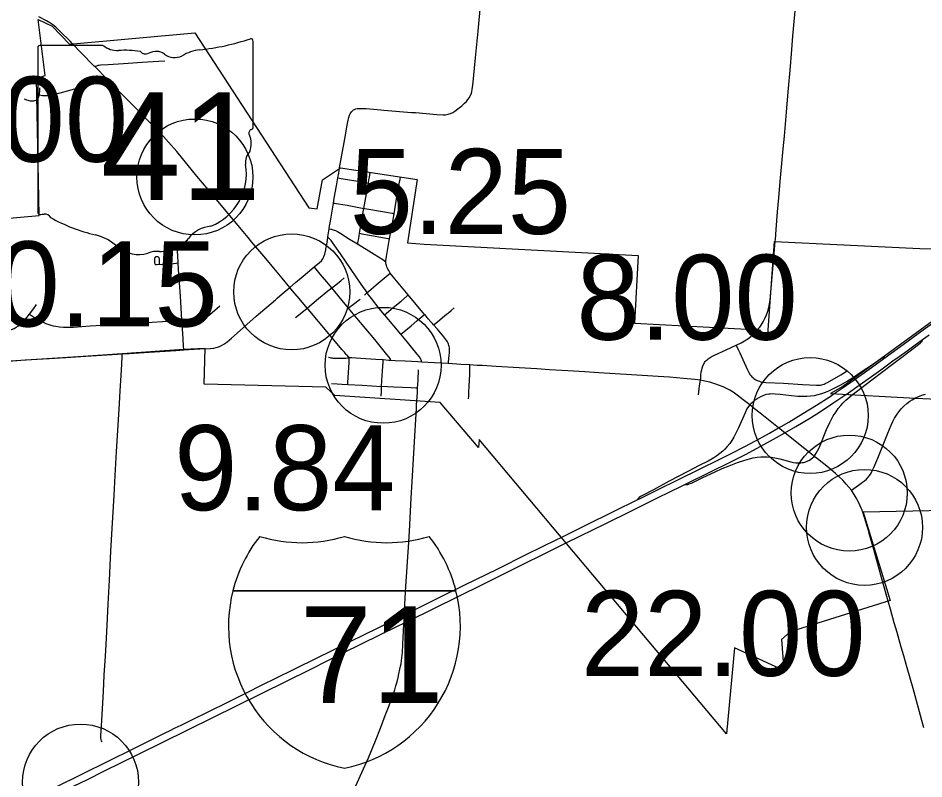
# Model space of a CAD drawing. Extents: x 1597222 to 1925846, y 496284 to 911751.
# Drawn here: x 1665653 to 1677369, y 597821 to 607664 of the extents above; entities that cross this region are included whole.
import ezdxf

# ---------------------------------------------------------------- set-up
doc = ezdxf.new("R2010")
doc.units = 0
for name, color, linetype in [('Default', 7, 'Continuous'), ('GM_X_City_Street', 7, 'Continuous'), ('GM_X_Corporation', 7, 'Continuous'), ('GM_X_County_Road', 7, 'Continuous'), ('GM_X_Interchange_Ramps', 7, 'Continuous'), ('GM_X_Interstate_Route', 7, 'Continuous'), ('GM_X_Interstate_Shield', 7, 'Continuous'), ('GM_X_State_Route', 7, 'Continuous'), ('GM_X_State_Shield', 7, 'Continuous'), ('GM_X_Township_Road', 7, 'Continuous')]:
    doc.layers.add(name, color=color, linetype=linetype)

msp = doc.modelspace()

# ---------------------------------------------------------------- linework, layer by layer
at = {"layer": 'Default'}
for centre in [(1667939, 605609), (1667939, 605609), (1669192, 604122), (1669192, 604122), (1669192, 604122), (1669192, 604122), (1670374, 603172), (1670374, 603172), (1675899, 602522), (1675899, 602522), (1676404, 601519), (1676404, 601519), (1676602, 601075), (1676602, 601075), (1666460, 597780), (1666460, 597780)]:
    msp.add_circle(centre, 750, dxfattribs=at)
at = {"layer": 'GM_X_City_Street'}
for points in [[(1666641, 607041), (1666672, 607049), (1666688, 607054), (1666701, 607056), (1666720, 607059), (1666818, 607066), (1667014, 607078), (1667258, 607094), (1667470, 607107), (1667552, 607113)], [(1665928, 606671), (1665968, 606664), (1665983, 606662), (1666000, 606661), (1666033, 606661), (1666065, 606665), (1666114, 606675), (1666195, 606696), (1666385, 606749), (1666626, 606814), (1666755, 606849), (1666811, 606868)], [(1665928, 606671), (1665929, 606681), (1665934, 606729), (1665935, 606761)], [(1665733, 606621), (1665762, 606608), (1665777, 606602), (1665793, 606598), (1665808, 606594), (1665823, 606593), (1665839, 606593), (1665855, 606595), (1665870, 606598), (1665884, 606604), (1665897, 606612), (1665907, 606624), (1665915, 606637), (1665922, 606651), (1665926, 606662), (1665928, 606671)], [(1670183, 605530), (1670190, 605571), (1670197, 605608), (1670207, 605668)], [(1669789, 605598), (1669830, 605591), (1670103, 605544), (1670183, 605530)], [(1670125, 605203), (1670150, 605345), (1670183, 605530)], [(1670183, 605530), (1670343, 605501), (1670472, 605479), (1670553, 605463), (1670573, 605459)], [(1670573, 605459), (1670578, 605490), (1670588, 605548), (1670593, 605577), (1670599, 605609)], [(1670516, 605134), (1670524, 605186), (1670544, 605298), (1670558, 605379), (1670573, 605459)], [(1669732, 605271), (1669745, 605269), (1669767, 605266), (1669799, 605261), (1669911, 605242), (1670125, 605203)], [(1670070, 604880), (1670075, 604909), (1670113, 605135), (1670125, 605203)], [(1670125, 605203), (1670136, 605201), (1670393, 605156), (1670490, 605139), (1670516, 605134)], [(1670458, 604810), (1670495, 605011), (1670516, 605134)], [(1669676, 604938), (1669696, 604934), (1669707, 604932), (1669717, 604929), (1669728, 604927), (1669742, 604922), (1669757, 604917), (1669786, 604902), (1669828, 604877), (1669939, 604806), (1670023, 604755), (1670042, 604743)], [(1670167, 604112), (1670090, 604223), (1669961, 604412), (1669823, 604614), (1669749, 604720), (1669720, 604761), (1669700, 604786), (1669674, 604818), (1669661, 604833)], [(1670042, 604743), (1670045, 604757), (1670050, 604779), (1670058, 604811), (1670070, 604880)], [(1670070, 604880), (1670099, 604874), (1670196, 604856), (1670390, 604821), (1670439, 604813), (1670458, 604810)], [(1670042, 604743), (1670190, 604652), (1670259, 604609), (1670370, 604541), (1670410, 604513)], [(1670410, 604513), (1670411, 604528), (1670413, 604550), (1670416, 604578), (1670431, 604658), (1670454, 604787), (1670458, 604810)], [(1667723, 604496), (1667718, 604592), (1667710, 604691)], [(1667481, 604482), (1667480, 604531), (1667480, 604547), (1667480, 604551), (1667479, 604557), (1667477, 604563), (1667472, 604569), (1667468, 604572), (1667464, 604574), (1667461, 604575), (1667456, 604576), (1667449, 604577), (1667444, 604577), (1667441, 604577), (1667437, 604577), (1667434, 604575), (1667430, 604573), (1667426, 604570), (1667422, 604565), (1667420, 604561), (1667418, 604555), (1667416, 604549), (1667416, 604545), (1667415, 604533), (1667415, 604522), (1667415, 604508), (1667416, 604500), (1667419, 604491), (1667422, 604485), (1667424, 604482), (1667428, 604479), (1667431, 604477), (1667434, 604476), (1667438, 604476), (1667443, 604475), (1667451, 604475), (1667663, 604491), (1667696, 604494), (1667723, 604496)], [(1667771, 603755), (1667761, 603917), (1667751, 604065), (1667728, 604411), (1667723, 604496)], [(1670465, 604364), (1670456, 604380), (1670446, 604397), (1670437, 604416), (1670430, 604431), (1670424, 604447), (1670419, 604463), (1670414, 604478), (1670411, 604497), (1670410, 604513)], [(1669709, 604174), (1669646, 604251), (1669560, 604352), (1669507, 604415), (1669482, 604445)], [(1670167, 604112), (1670184, 604126), (1670285, 604214), (1670465, 604364)], [(1670698, 604083), (1670527, 604291), (1670465, 604364)], [(1669709, 604174), (1669744, 604201), (1669826, 604266), (1669872, 604304)], [(1669392, 603913), (1669452, 603964), (1669539, 604035), (1669661, 604135), (1669709, 604174)], [(1669926, 603912), (1669843, 604010), (1669709, 604174)], [(1670133, 604081), (1670167, 604112)], [(1670391, 603827), (1670324, 603909), (1670223, 604037), (1670174, 604102), (1670167, 604112)], [(1669926, 603912), (1669941, 603924), (1669991, 603962), (1670066, 604021), (1670078, 604030)], [(1670391, 603827), (1670417, 603848), (1670505, 603920), (1670607, 604002), (1670680, 604067), (1670698, 604083)], [(1670910, 603831), (1670698, 604083)], [(1665799, 603835), (1665842, 603890), (1665890, 603957)], [(1667771, 603755), (1667806, 603757), (1667871, 603761), (1667970, 603767), (1668003, 603771), (1668019, 603774), (1668036, 603779), (1668052, 603784), (1668082, 603797), (1668111, 603813), (1668139, 603833), (1668164, 603854), (1668263, 603941)], [(1669241, 603790), (1669367, 603892), (1669392, 603913)], [(1670472, 603235), (1670464, 603260), (1670453, 603276), (1670421, 603313), (1670319, 603443), (1670267, 603506), (1670035, 603784), (1669926, 603912)], [(1671026, 603696), (1671055, 603719), (1671082, 603739), (1671170, 603811), (1671196, 603832), (1671219, 603851), (1671256, 603882), (1671294, 603916)], [(1665330, 603602), (1665359, 603603), (1665408, 603604), (1665458, 603609), (1665506, 603617), (1665538, 603625), (1665569, 603637), (1665600, 603650), (1665629, 603665), (1665657, 603683), (1665683, 603703), (1665708, 603724), (1665730, 603746), (1665744, 603763), (1665752, 603774), (1665799, 603835)], [(1665799, 603835), (1665824, 603818), (1665837, 603808), (1665878, 603780), (1665922, 603755), (1665966, 603734), (1666012, 603715), (1666075, 603693), (1666107, 603684), (1666140, 603678), (1666189, 603671), (1666238, 603666), (1666288, 603664), (1666370, 603667), (1666584, 603681), (1666896, 603700), (1667143, 603717), (1667324, 603728), (1667587, 603745), (1667734, 603753), (1667771, 603755)], [(1670603, 603575), (1670512, 603683), (1670397, 603821), (1670391, 603827)], [(1670603, 603575), (1670621, 603589), (1670736, 603684), (1670812, 603748), (1670888, 603812), (1670910, 603831)], [(1671026, 603696), (1671012, 603711), (1670990, 603735), (1670958, 603772), (1670917, 603824), (1670910, 603831)], [(1667795, 603371), (1667792, 603423), (1667782, 603588), (1667772, 603736), (1667771, 603755)], [(1671220, 603194), (1671222, 603216), (1671229, 603299), (1671231, 603334), (1671233, 603368), (1671231, 603398), (1671229, 603414), (1671225, 603429), (1671221, 603445), (1671215, 603459), (1671207, 603474), (1671199, 603487), (1671160, 603540), (1671076, 603639), (1671026, 603696)], [(1670870, 603214), (1670871, 603229), (1670867, 603242), (1670863, 603252), (1670843, 603282), (1670813, 603317), (1670741, 603407), (1670690, 603470), (1670603, 603575)], [(1674940, 603433), (1675004, 603463), (1675048, 603487), (1675090, 603513), (1675129, 603543), (1675158, 603569), (1675181, 603591), (1675209, 603621), (1675220, 603634)], [(1674479, 602981), (1674482, 603012), (1674485, 603057), (1674487, 603074), (1674489, 603088), (1674495, 603114), (1674501, 603136), (1674511, 603166), (1674525, 603195), (1674533, 603209), (1674542, 603222), (1674553, 603234), (1674564, 603245), (1674577, 603255), (1674590, 603265), (1674618, 603281), (1674661, 603304), (1674810, 603373), (1674940, 603433)], [(1674940, 603433), (1674967, 603377), (1674988, 603332), (1675084, 603122), (1675106, 603078), (1675124, 603050), (1675134, 603037), (1675145, 603025), (1675157, 603014), (1675169, 603003), (1675183, 602994), (1675197, 602985), (1675211, 602977), (1675226, 602970), (1675242, 602965), (1675258, 602960), (1675290, 602954), (1675323, 602950), (1675553, 602939), (1675800, 602924), (1675981, 602915), (1676014, 602915), (1676030, 602916), (1676046, 602919), (1676062, 602923), (1676078, 602928), (1676093, 602935), (1676122, 602950), (1676294, 603047), (1676378, 603100)], [(1669668, 603279), (1669683, 603274), (1669698, 603270), (1669715, 603267), (1669728, 603265), (1669740, 603264), (1669761, 603264), (1669809, 603263), (1669859, 603264), (1669891, 603265), (1669912, 603267), (1669937, 603270)], [(1669916, 602924), (1669918, 602950), (1669926, 603080), (1669934, 603210), (1669937, 603270)], [(1671480, 602739), (1671482, 602773), (1671485, 602823), (1671488, 602904), (1671495, 603054), (1671497, 603118), (1671498, 603156), (1671498, 603177)], [(1670820, 602877), (1670827, 602979), (1670833, 603114)], [(1674455, 602789), (1674465, 602908), (1674479, 602981)], [(1669708, 602936), (1669778, 602931), (1669842, 602928), (1669916, 602924)], [(1669916, 602924), (1670101, 602913), (1670355, 602899)], [(1670351, 602773), (1670353, 602839), (1670355, 602899)]]:
    msp.add_lwpolyline(points, dxfattribs=at)
at = {"layer": 'GM_X_Corporation'}
for points in [[(1664571, 604990), (1665925, 605111), (1665891, 606881), (1666004, 606922), (1665913, 607646), (1666092, 607560), (1666317, 607328), (1667939, 607472), (1669413, 605210), (1669522, 605195), (1669588, 605574), (1669821, 605726), (1670815, 605575), (1670690, 604758), (1670905, 604739), (1673675, 604592), (1673628, 603718), (1675241, 603632), (1675327, 603511), (1675347, 603509), (1675411, 604413), (1675419, 604540), (1675435, 604774), (1677319, 604682), (1677768, 604673)], [(1677671, 603881), (1676320, 602899), (1676161, 602808), (1677259, 602749), (1677731, 602724)], [(1677655, 601292), (1676583, 601273), (1676933, 600130), (1675641, 599722), (1675527, 599624), (1675558, 599225), (1674921, 599515), (1674815, 598405), (1672746, 600866), (1671617, 602210), (1671609, 602108), (1671110, 602693), (1669750, 602781), (1669632, 602889), (1668058, 602929), (1668072, 603390), (1667791, 603376), (1666999, 603320), (1666560, 603289), (1665960, 603252), (1665349, 603213)]]:
    msp.add_lwpolyline(points, dxfattribs=at)
at = {"layer": 'GM_X_County_Road'}
for points in [[(1675445, 604774), (1675448, 604798), (1675458, 604929), (1675477, 605158), (1675493, 605338), (1675512, 605550), (1675541, 605877), (1675551, 605975), (1675566, 606138), (1675593, 606449), (1675615, 606711), (1675643, 607038), (1675657, 607201), (1675676, 607430), (1675716, 607904), (1675738, 608150), (1675755, 608362), (1675801, 608885), (1675813, 609029)], [(1675220, 603634), (1675234, 603651), (1675246, 603666), (1675264, 603691), (1675290, 603734), (1675313, 603778), (1675333, 603824), (1675350, 603871), (1675363, 603919), (1675373, 603968), (1675380, 604017), (1675445, 604774)]]:
    msp.add_lwpolyline(points, dxfattribs=at)
at = {"layer": 'GM_X_Interchange_Ramps'}
for points in [[(1675951, 601994), (1675977, 602034), (1675995, 602067), (1676020, 602115), (1676111, 602340), (1676151, 602430), (1676173, 602474), (1676197, 602517), (1676233, 602572), (1676262, 602612), (1676293, 602650), (1676326, 602687), (1676360, 602722), (1676410, 602765), (1676444, 602793), (1676474, 602817), (1676697, 602986), (1676944, 603172), (1677100, 603289), (1677323, 603458), (1677339, 603474), (1677345, 603480), (1677349, 603487), (1677352, 603496), (1677353, 603507)], [(1676869, 603273), (1676854, 603271), (1676839, 603267), (1676825, 603261), (1676809, 603252), (1676729, 603197), (1676534, 603064), (1676466, 603019), (1676382, 602968), (1676282, 602911), (1676195, 602866), (1676136, 602838), (1676091, 602819), (1676045, 602802), (1675998, 602789), (1675950, 602778), (1675901, 602771), (1675853, 602768), (1675803, 602767), (1675738, 602770), (1675657, 602778), (1675511, 602795), (1675445, 602800), (1675413, 602801), (1675380, 602800), (1675364, 602799), (1675332, 602793), (1675316, 602789), (1675285, 602778), (1675256, 602763), (1675227, 602747), (1675173, 602711), (1675155, 602695), (1675135, 602678), (1675116, 602660)], [(1675116, 602660), (1675100, 602637), (1675081, 602607), (1675058, 602557), (1674972, 602361), (1674943, 602301), (1674912, 602243), (1674886, 602201), (1674857, 602161), (1674826, 602123), (1674793, 602086), (1674769, 602063), (1674731, 602032), (1674691, 602002), (1674650, 601975), (1674579, 601933), (1674461, 601874), (1674317, 601800), (1674074, 601671), (1673871, 601563), (1673731, 601489), (1673704, 601474), (1673687, 601463), (1673673, 601449), (1673662, 601432)], [(1674279, 601631), (1674301, 601629), (1674308, 601630), (1674317, 601631), (1674335, 601637), (1674363, 601649), (1674509, 601720), (1674668, 601795), (1674759, 601835), (1674850, 601873), (1674958, 601913), (1675052, 601944), (1675115, 601963), (1675163, 601974), (1675212, 601982), (1675261, 601987), (1675294, 601989), (1675343, 601988), (1675392, 601983), (1675441, 601975), (1675505, 601961), (1675649, 601923), (1675681, 601916), (1675714, 601912), (1675746, 601910), (1675779, 601911), (1675796, 601913), (1675812, 601916), (1675828, 601920), (1675859, 601931), (1675888, 601946), (1675927, 601976), (1675951, 601994)]]:
    msp.add_lwpolyline(points, dxfattribs=at)
at = {"layer": 'GM_X_Interstate_Route'}
for points in [[(1666117, 597705), (1666485, 597888), (1667151, 598216), (1667286, 598282), (1667563, 598419), (1667611, 598444), (1667686, 598481), (1667761, 598518), (1667918, 598595), (1668093, 598680), (1668391, 598828), (1668640, 598951), (1668777, 599019), (1669021, 599141), (1669199, 599227), (1669554, 599403), (1669671, 599460), (1669991, 599619), (1670083, 599664), (1670152, 599698), (1670285, 599764), (1670649, 599944), (1671081, 600157), (1671424, 600327), (1671856, 600540), (1672233, 600727), (1672620, 600918), (1672679, 600946), (1672989, 601100), (1673362, 601284), (1673662, 601432), (1673708, 601454), (1673923, 601559), (1674204, 601700), (1674456, 601824), (1674737, 601962), (1674867, 602026), (1675052, 602120), (1675192, 602195), (1675288, 602248), (1675372, 602294), (1675490, 602361), (1675525, 602381), (1675623, 602437), (1675805, 602548), (1675982, 602656), (1676155, 602769), (1676208, 602806), (1676324, 602886), (1676469, 602984), (1676662, 603121), (1676835, 603248), (1676869, 603273), (1677103, 603441), (1677359, 603629), (1677679, 603859)], [(1676363, 602796), (1676534, 602915), (1676692, 603028), (1676811, 603114), (1676968, 603228), (1677048, 603286), (1677151, 603361), (1677258, 603438), (1677353, 603507), (1677438, 603568)], [(1672742, 600873), (1672926, 600964), (1673246, 601123), (1673588, 601291), (1673966, 601477), (1674041, 601514), (1674279, 601631), (1674312, 601647), (1674870, 601924), (1675061, 602020), (1675261, 602125), (1675462, 602236), (1675570, 602298), (1675712, 602380), (1675901, 602494), (1676031, 602576), (1676204, 602689), (1676348, 602786), (1676363, 602796)], [(1670626, 599828), (1670644, 599837), (1670708, 599868), (1671352, 600186), (1671658, 600338), (1672126, 600569), (1672508, 600758), (1672742, 600873)], [(1664380, 596744), (1665760, 597422), (1666351, 597716), (1666379, 597730), (1666540, 597810), (1666769, 597923), (1667210, 598141), (1669437, 599241), (1669660, 599351), (1669859, 599450), (1670569, 599801), (1670626, 599828)]]:
    msp.add_lwpolyline(points, dxfattribs=at)
at = {"layer": 'GM_X_Interstate_Shield'}
for p, q in [((1668432, 600256), (1671317, 600256)), ((1671317, 600256), (1668432, 600256)), ((1671317, 600256), (1668432, 600256))]:
    msp.add_line(p, q, dxfattribs=at)
for centre, start, end in [((1670249, 599796), 141.669, 165.8066), ((1669327, 602752), 253.0091, 286.9909), ((1670422, 602752), 253.0091, 286.9909), ((1669499, 599796), 14.1934, 38.331), ((1670249, 599796), 165.8066, 258.463), ((1669499, 599796), 281.537, 14.1934)]:
    msp.add_arc(centre, 1875, start, end, dxfattribs=at)
at = {"layer": 'GM_X_State_Route'}
for points in [[(1669812, 605729), (1669879, 606103), (1669911, 606280), (1669923, 606345), (1669930, 606377), (1669940, 606409), (1669947, 606425), (1669955, 606439), (1669965, 606453), (1669977, 606466), (1669990, 606476), (1670005, 606484), (1670021, 606490), (1670038, 606494), (1670054, 606496), (1670088, 606497), (1670154, 606493), (1670343, 606477), (1670382, 606474), (1670742, 606445), (1670791, 606441), (1671069, 606418), (1671150, 606414), (1671183, 606415), (1671199, 606417), (1671214, 606420), (1671230, 606424), (1671245, 606430), (1671274, 606444), (1671302, 606460), (1671341, 606489), (1671392, 606530), (1671428, 606563), (1671451, 606586), (1671472, 606611), (1671491, 606638), (1671498, 606652), (1671511, 606681), (1671520, 606712), (1671527, 606744), (1671533, 606792), (1671567, 607152), (1671602, 607494), (1671639, 607870)], [(1666356, 607332), (1666324, 607364), (1666198, 607491), (1666139, 607547), (1666102, 607578), (1666062, 607605), (1666020, 607630), (1665919, 607682)], [(1668627, 604827), (1668563, 604904), (1668322, 605193), (1668113, 605446), (1667966, 605621), (1667705, 605937), (1667599, 606061), (1667532, 606133), (1667396, 606275), (1667155, 606520), (1666983, 606695), (1666811, 606868), (1666641, 607041), (1666637, 607044), (1666466, 607220), (1666356, 607332)], [(1669789, 605598), (1669800, 605657), (1669812, 605729)], [(1669631, 604666), (1669633, 604675), (1669646, 604738), (1669655, 604786), (1669661, 604833), (1669676, 604938), (1669678, 604948), (1669696, 605061), (1669732, 605271), (1669743, 605335), (1669771, 605496), (1669789, 605598)], [(1669168, 604179), (1669067, 604301), (1668962, 604427), (1668857, 604552), (1668678, 604766), (1668627, 604827)], [(1669168, 604179), (1669240, 604242), (1669340, 604325), (1669482, 604445), (1669553, 604503), (1669576, 604526), (1669586, 604538), (1669595, 604551), (1669602, 604565), (1669608, 604580), (1669619, 604612), (1669631, 604666)], [(1669005, 604042), (1669068, 604095), (1669168, 604179)], [(1669537, 603739), (1669406, 603897), (1669392, 603913), (1669289, 604036), (1669204, 604137), (1669168, 604179)], [(1668563, 603655), (1668574, 603665), (1668733, 603806), (1668980, 604021), (1669005, 604042)], [(1668256, 603414), (1668285, 603427), (1668313, 603444), (1668352, 603473), (1668414, 603525), (1668563, 603655)], [(1669912, 603298), (1669910, 603301), (1669895, 603314), (1669873, 603340), (1669839, 603377), (1669649, 603605), (1669537, 603739)], [(1664747, 603176), (1664876, 603184), (1665106, 603199), (1665354, 603215), (1665417, 603219), (1665744, 603241), (1666055, 603260), (1666268, 603274), (1666530, 603290), (1666940, 603317), (1667000, 603321), (1667087, 603327), (1667284, 603339), (1667415, 603347), (1667693, 603365), (1667795, 603371), (1667857, 603375), (1668004, 603384), (1668135, 603391), (1668184, 603396), (1668216, 603401), (1668231, 603406), (1668256, 603414)], [(1670374, 603242), (1670281, 603249), (1670084, 603260), (1670025, 603264), (1669971, 603267), (1669937, 603270), (1669912, 603298)], [(1670819, 602856), (1670820, 602877), (1670796, 602878), (1670735, 602879), (1670511, 602889), (1670432, 602894), (1670355, 602899), (1670359, 602976), (1670366, 603097), (1670370, 603162), (1670373, 603209), (1670374, 603242)], [(1671657, 603168), (1671592, 603171), (1671498, 603177), (1671380, 603184), (1671220, 603194), (1671216, 603194), (1671037, 603205), (1670870, 603214), (1670824, 603215), (1670660, 603225), (1670530, 603232), (1670472, 603235), (1670448, 603236), (1670374, 603242)], [(1674479, 602981), (1674406, 602989), (1674259, 603003), (1674079, 603018), (1673932, 603029), (1673588, 603049), (1673163, 603074), (1672983, 603088), (1672836, 603097), (1672688, 603106), (1672525, 603115), (1672361, 603125), (1672132, 603139), (1671837, 603157), (1671657, 603168)], [(1675178, 602610), (1675116, 602660), (1675033, 602726), (1674955, 602786), (1674901, 602823), (1674859, 602849), (1674816, 602873), (1674771, 602894), (1674725, 602912), (1674663, 602934), (1674600, 602953), (1674536, 602969), (1674479, 602981)], [(1670812, 602711), (1670818, 602822), (1670819, 602856)], [(1670718, 601104), (1670719, 601111), (1670738, 601455), (1670749, 601668), (1670775, 602110), (1670806, 602616), (1670808, 602658), (1670812, 602711)], [(1676435, 601555), (1676523, 601620), (1676576, 601658), (1676602, 601679), (1676625, 601701), (1676647, 601725), (1676668, 601750), (1676686, 601777), (1676702, 601806), (1676723, 601850), (1676773, 601971), (1676901, 602292), (1676945, 602398), (1676966, 602443), (1676989, 602487), (1677015, 602529), (1677045, 602569), (1677077, 602607), (1677111, 602643), (1677148, 602676), (1677188, 602706), (1677216, 602724), (1677262, 602750), (1677311, 602772), (1677342, 602784), (1677390, 602799)], [(1675993, 601962), (1675951, 601994), (1675931, 602011), (1675725, 602173), (1675570, 602298), (1675490, 602361), (1675251, 602552), (1675178, 602610)], [(1676435, 601555), (1676365, 601635), (1676321, 601684), (1676274, 601730), (1676225, 601774), (1676136, 601848), (1675993, 601962)], [(1676578, 601274), (1676566, 601305), (1676558, 601323), (1676531, 601383), (1676493, 601456), (1676435, 601555)], [(1676655, 601021), (1676578, 601274)], [(1670487, 598864), (1670498, 598895), (1670524, 598972), (1670540, 599023), (1670554, 599075), (1670568, 599134), (1670578, 599181), (1670592, 599241), (1670600, 599278), (1670607, 599310), (1670612, 599351), (1670624, 599457), (1670629, 599561), (1670634, 599657), (1670638, 599722), (1670644, 599837), (1670645, 599851), (1670649, 599944), (1670656, 600083), (1670670, 600310), (1670705, 600882), (1670718, 601104)], [(1676908, 600121), (1676827, 600410), (1676774, 600600), (1676720, 600789), (1676663, 600995), (1676655, 601021)], [(1677369, 598483), (1677299, 598736), (1677229, 598989), (1677151, 599257), (1677108, 599415), (1677076, 599525), (1677023, 599715), (1676987, 599841), (1676939, 600015), (1676908, 600121)], [(1669951, 597581), (1670185, 598095), (1670275, 598315), (1670341, 598478), (1670402, 598640), (1670453, 598769), (1670487, 598864)]]:
    msp.add_lwpolyline(points, dxfattribs=at)
at = {"layer": 'GM_X_State_Shield'}
for p, q in [((1665908, 607275), (1665908, 605162)), ((1666750, 607311), (1665935, 607311)), ((1668692, 606258), (1668692, 607364)), ((1668692, 606259), (1668692, 606258))]:
    msp.add_line(p, q, dxfattribs=at)
for centre, radius, start, end in [((1667700, 610192), 2953, 275.8445, 288.9065), ((1668661, 607368), 31, 351.8621, 97.738), ((1665939, 607280), 32.3, 98.1301, 188.1301), ((1666945, 607557), 313, 231.6195, 271.1119), ((1667048, 606125), 1123, 80.4867, 94.9883), ((1667303, 607290), 90.3, 219.7921, 297.1024), ((1667436, 607046), 188, 54.4667, 119.1411), ((1667678, 607381), 226, 233.8562, 294.8282), ((1668077, 606666), 594, 97.3462, 120.7689), ((1668685, 606177), 48, 107.944, 210.337), ((1668659, 606254), 33.2, 289.6038, 7.7341), ((1668380, 606037), 288, 340.033, 23.6496), ((1668803, 605796), 210, 136.8065, 186.9296), ((1667866, 605655), 739, 292.3089, 8.9858), ((1665940, 605157), 32.5, 171.9584, 258.3066), ((1665945, 605373), 248, 267.339, 280.6039), ((1665996, 605040), 89.5, 29.7484, 93.2717), ((1667126, 606939), 2132, 240.4129, 257.1985), ((1668177, 604568), 404, 94.4031, 142.5768), ((1666490, 604212), 667, 47.1842, 75.836), ((1667664, 604957), 239, 282.8732, 323.2771), ((1667212, 605029), 423, 230.7004, 286.2918), ((1667487, 604871), 226, 268.777, 315.5493), ((1667692, 604666), 63.5, 65.7517, 132.6484), ((1667457, 604299), 348, 85.6951, 111.2099)]:
    msp.add_arc(centre, radius, start, end, dxfattribs=at)
at = {"layer": 'GM_X_Township_Road'}
msp.add_lwpolyline([(1666740, 598301), (1666731, 598315), (1666725, 598331), (1666723, 598347), (1666723, 598379), (1666734, 598576), (1666756, 598952), (1666767, 599164), (1666783, 599409), (1666797, 599638), (1666810, 599900), (1666818, 600080), (1666834, 600391), (1666854, 600767), (1666870, 601061), (1666894, 601486), (1666908, 601748), (1666927, 602058), (1666952, 602467), (1666964, 602679), (1666974, 602843), (1666986, 603039), (1666994, 603186), (1666999, 603284), (1667000, 603321)], dxfattribs=at)

# ---------------------------------------------------------------- texts
at = {"layer": 'Default'}
for s, p in [('24.00', (1663395, 605806)), ('24.00', (1663395, 605806)), ('5.25', (1669942, 604872)), ('5.25', (1669942, 604872)), ('10.15', (1664555, 603675)), ('10.15', (1664555, 603675)), ('8.00', (1672875, 603503)), ('8.00', (1672875, 603503)), ('9.84', (1667671, 601297)), ('9.84', (1667671, 601297)), ('22.00', (1672933, 599154)), ('22.00', (1672933, 599154))]:
    msp.add_text(s, height=1100, dxfattribs=at).set_placement(p)
at = {"layer": 'GM_X_Interstate_Shield'}
msp.add_text('71', height=1250, dxfattribs=at).set_placement((1669297, 598803))
at = {"layer": 'GM_X_State_Shield'}
msp.add_text('41', height=1392.2, dxfattribs=at).set_placement((1666722, 605311))

doc.saveas('drawing.dxf')
